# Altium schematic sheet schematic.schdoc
size 250 x 147 mm
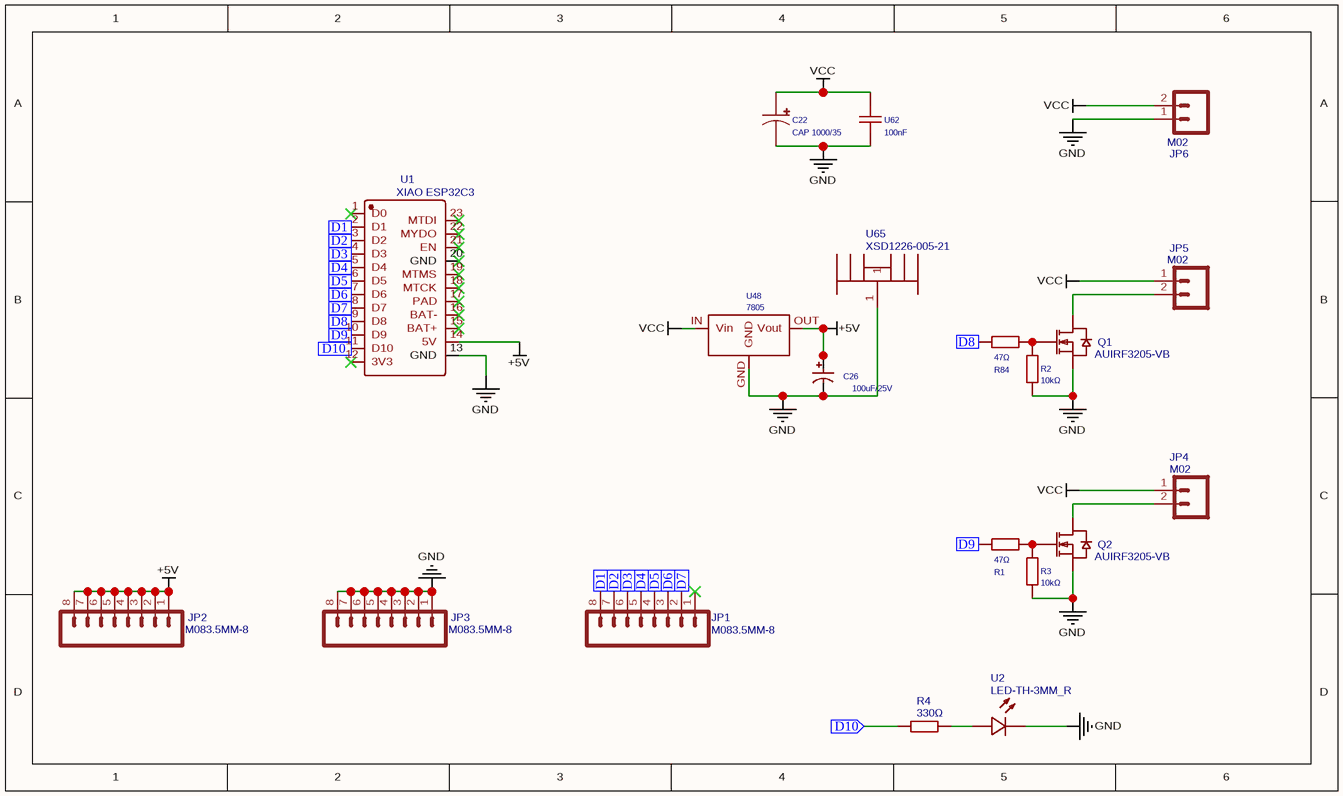
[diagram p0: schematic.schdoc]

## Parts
C22  CAP 1000/35  [CAP 1000/35]
C26  100uF/25V  [CAP-TH_BD5.0-P2.00-D0.8-FD]
JP1  M083.5MM-8  [SCREWTERMINAL-3.5MM-8]
JP2  M083.5MM-8  [SCREWTERMINAL-3.5MM-8]
JP3  M083.5MM-8  [SCREWTERMINAL-3.5MM-8]
JP4  M02  [SCREWTERMINAL-5MM-2]
JP5  M02  [SCREWTERMINAL-5MM-2]
JP6  M02  [SCREWTERMINAL-5MM-2]
Q1  AUIRF3205-VB  [TO-220-3_L10.0-W4.6-P2.54-L]
Q2  AUIRF3205-VB  [TO-220-3_L10.0-W4.6-P2.54-L]
R1  47Ω  [RES-TH_BD2.3-L6.5-P10.50-D0.5]
R2  10kΩ  [RES-TH_BD2.3-L6.5-P10.50-D0.5]
R3  10kΩ  [RES-TH_BD2.3-L6.5-P10.50-D0.5]
R4  330Ω  [RES-TH_BD2.3-L6.5-P10.50-D0.5]
R84  47Ω  [RES-TH_BD2.3-L6.5-P10.50-D0.5]
U1  XIAO ESP32C3  [CONN-SMD_XIAO_ESP32C3]
U2  LED-TH-3MM_R  [LED-TH_BD5.4-P2.54-FD_RED]
U48  7805  [7805]
U62  100nF  [CAP-TH_L5.5-W3.5-P5.00-D0.5]
U65  XSD1226-005-21  [HEATSINK-TH_L15.5-W10.5-XSD1226-005]

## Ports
D1 (in), D2 (in), D3 (in), D4 (in), D5 (in), D6 (in), D7 (in), D8 (in), D9 (in), D10 (in)

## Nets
+5V: C26.1 JP2.1 JP2.2 JP2.3 JP2.4 JP2.5 JP2.6 JP2.7 JP2.8 U1.14(5V) U48.OUT(Vout)
GND: C22.2 C26.2 JP3.1 JP3.2 JP3.3 JP3.4 JP3.5 JP3.6 JP3.7 JP3.8 JP6.1 Q1.3(S) Q2.3(S) R2.1 R3.1 U1.13(GND) U2.2 U48.GND U62.1 U65.1
VCC: C22.1 JP4.1 JP5.1 JP6.2 U48.IN(Vin) U62.2
D1: JP1.8 U1.2(D1) ; port D1
D2: JP1.7 U1.3(D2) ; port D2
D3: JP1.6 U1.4(D3) ; port D3
D4: JP1.5 U1.5(D4) ; port D4
D5: JP1.4 U1.6(D5) ; port D5
D6: JP1.3 U1.7(D6) ; port D6
D7: JP1.2 U1.8(D7) ; port D7
D8: R84.1 U1.9(D8) ; port D8
D9: R1.1 U1.10(D9) ; port D9
D10: R4.2 U1.11(D10) ; port D10
NetJP4_2: JP4.2 Q2.2(D)
NetJP5_2: JP5.2 Q1.2(D)
NetQ1_1: Q1.1(G) R2.2 R84.2
NetQ2_1: Q2.1(G) R1.2 R3.2
NetR4_1: R4.1 U2.1

Not connected (* = marked no-connect by the designer): JP1 1*; U1 1(D0)* 12(3V3)* 15(BAT+)* 16(BAT-)* 17(PAD)* 18(MTCK)* 19(MTMS)* 20(GND)* 21(EN)* 22(MYDO)* 23(MTDI)*

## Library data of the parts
C22 = CAP 1000/35: Contributor: wilisona8950
C26 = 100uF/25V: nameAlias: Value
JP1-JP3 = M083.5MM-8: description: Header 8; Contributor: SparkFun
JP4-JP6 = M02: Contributor: SparkFun
Q1 Q2 = AUIRF3205-VB: Manufacturer: VBsemi(微碧半导体); Contributor: lcsc
R1 R84 = 47Ω: nameAlias: Value; Contributor: LCSC
R2 R3 = 10kΩ: nameAlias: Value; Contributor: LCSC
R4 = 330Ω: Manufacturer: CCO(千志电子); Manufacturer Part: CF1/4W-10KΩ±5% T; nameAlias: Value; Contributor: LCSC
U1 = XIAO ESP32C3: Manufacturer: null; Contributor: lcsc
U2 = LED-TH-3MM_R: Manufacturer: null; Contributor: LCSC
U48 = 7805: Contributor: wilisona8950
U62 = 100nF: Contributor: lcsc; nameAlias: Value
U65 = XSD1226-005-21: Manufacturer: XSD(鑫顺达); Contributor: lcsc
